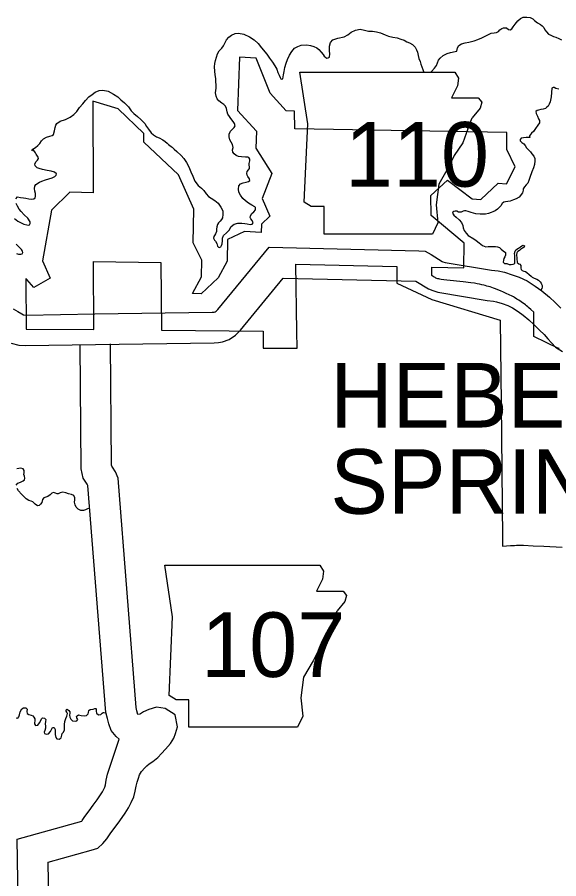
# Model space of a CAD drawing. Extents: x 1212896 to 1368412, y 378476 to 478763.
# Drawn here: x 1234255 to 1239571, y 464301 to 472756 of the extents above; entities that cross this region are included whole.
import ezdxf

# ---------------------------------------------------------------- set-up
doc = ezdxf.new("R2010")
doc.units = 0
for name, color, linetype in [('Level 10', 7, 'Continuous'), ('Level 21', 7, 'Continuous'), ('Level 6', 7, 'Continuous'), ('Level 9', 7, 'Continuous')]:
    doc.layers.add(name, color=color, linetype=linetype)

msp = doc.modelspace()

# ---------------------------------------------------------------- linework, layer by layer
at = {"layer": 'Level 10'}
for points in [[(1234214.4, 469894.6), (1234260.5, 469868.1), (1234301.2, 469844.9), (1234317.3, 469835), (1234318.7, 469834.6), (1234342.9, 469833.1), (1235017.8, 469844.2), (1236168.7, 469859.8), (1236189.6, 469862.4), (1236197.3, 469863.6), (1236206.4, 469869.9), (1236224.5, 469887.4), (1236727.1, 470498.3), (1238195.9, 470464.7), (1238259.5, 470461.2), (1238317.3, 470426.4), (1238425.5, 470360.3), (1238434.6, 470356.7), (1238455.1, 470350.3), (1238911.2, 470273.7), (1238975.9, 470266.3), (1239037.7, 470254.7), (1239113.8, 470228.9), (1239183.7, 470204.8), (1239261.6, 470167.8), (1239340, 470117.4), (1239405.4, 470070.8), (1239479.7, 470009.5), (1239534.3, 469954.7), (1239591.9, 469901.1)], [(1234197.2, 469556.6), (1234270.3, 469537), (1234336.3, 469533), (1235022.2, 469544.3), (1236189.5, 469560.1), (1236230.4, 469565.2), (1236271.4, 469571.3), (1236334.5, 469593.7), (1236397.3, 469637.1), (1236445.3, 469683.6), (1236866.1, 470195), (1238169.3, 470165.3), (1238291.6, 470090.5), (1238335.1, 470073.5), (1238385.2, 470057.8), (1238869.2, 469976.6), (1238930.9, 469969.5), (1238961.5, 469963.7), (1239016.7, 469945.1), (1239070, 469926.6), (1239115.7, 469905), (1239171.8, 469868.9), (1239222.6, 469832.7), (1239277.4, 469787.4), (1239325.8, 469738.9), (1239383.2, 469685.5), (1239426.7, 469641.7), (1239463.4, 469600.5), (1239499.9, 469559.9), (1239539.7, 469517.7), (1239606.3, 469475.2)], [(1234267.2, 463883.5), (1234255.7, 464690.1), (1234887.9, 464865.5), (1234893.6, 464872.6), (1234919.8, 464911.7), (1234960.2, 464967.5), (1235001.2, 465023.2), (1235038.7, 465076.2), (1235066.1, 465115.1), (1235090.9, 465152.6), (1235106, 465180.6), (1235114.9, 465200.2), (1235120.5, 465224.1), (1235128.7, 465267.7), (1235140.3, 465326.1), (1235254.7, 465670.4), (1235224.8, 465697.4), (1235177.9, 465757.2), (1235154.7, 465822.2), (1235140.6, 465873.8), (1235125.8, 465932.4), (1234949.6, 468159.3), (1234940.5, 468172.4), (1234902.8, 468231.5), (1234882.1, 468323.5), (1234871.3, 469543.8)], [(1234567.2, 463887.2), (1234559, 464462.9), (1234981, 464580.1), (1235045.2, 464600.7), (1235097, 464647.4), (1235134.8, 464693.5), (1235166.1, 464740.2), (1235202.6, 464790.8), (1235244.4, 464847.6), (1235283.7, 464903), (1235313.9, 464945.9), (1235348.5, 464998.3), (1235375.1, 465047.6), (1235400.2, 465103.1), (1235414.1, 465161.9), (1235423.3, 465211), (1235430.9, 465249.3), (1235444.2, 465289.3), (1235456.8, 465321.6), (1235476.5, 465354.4), (1235506.2, 465389.6), (1235527.1, 465410.4), (1235549.1, 465427.5), (1235586.9, 465450.5), (1235636.9, 465491.1), (1235671.4, 465529), (1235711.2, 465572.4), (1235759.2, 465629.6), (1235790.9, 465681.2), (1235809.9, 465726.1), (1235827.2, 465792.8), (1235806.1, 465910.4), (1235707.9, 465972.1), (1235620.7, 465984.8), (1235548.1, 465963.2), (1235495.8, 465938.2), (1235464.7, 465918.5), (1235458.1, 465916.5), (1235440.6, 465914.1), (1235430.7, 465950.2), (1235422.9, 465981.2), (1235244.8, 468231.4), (1235221, 468294.6), (1235190.2, 468338.8), (1235183.9, 468348.6), (1235181.8, 468358.2), (1235171.3, 469549.1)]]:
    msp.add_lwpolyline(points, dxfattribs=at)
at = {"layer": 'Level 21'}
for p, q in [((1237106.7, 471710.6), (1237030.5, 472218.1)), ((1237030.5, 472218.1), (1238551.9, 472217.4)), ((1238551.9, 472217.4), (1238587, 472158.9)), ((1238553.2, 472218.1), (1238553.2, 472218.1)), ((1238587, 472158.9), (1238578.5, 472082.8)), ((1238578.5, 472082.8), (1238519.3, 471964.4)), ((1238519.3, 471964.4), (1238781.5, 471964.4)), ((1238781.5, 471964.4), (1238815.4, 471922.1)), ((1238815.4, 471922.1), (1238798.5, 471862.9)), ((1238798.5, 471862.9), (1238722.3, 471769.8)), ((1238680, 471659.8), (1238722.3, 471769.8)), ((1237072.8, 470940.8), (1237106.7, 471710.6)), ((1238680, 471659.8), (1238629.3, 471524.5)), ((1238629.3, 471524.5), (1238544.7, 471397.6)), ((1238544.7, 471397.6), (1238485.5, 471279.2)), ((1238485.5, 471279.2), (1238392.4, 471118.5)), ((1238392.4, 471118.5), (1238367.1, 470915.5)), ((1237140.5, 470898.5), (1237072.8, 470940.8)), ((1237267.4, 470898.5), (1237140.5, 470898.5)), ((1237267.4, 470627.9), (1237267.4, 470898.5)), ((1238367.1, 470915.5), (1238384, 470737.8)), ((1238384, 470737.8), (1238333.2, 470627.9)), ((1238333.2, 470627.9), (1237267.4, 470627.9)), ((1235780.3, 466870.3), (1235704.2, 467377.8)), ((1235704.2, 467377.8), (1237225.5, 467377.1)), ((1237225.5, 467377.1), (1237260.6, 467318.6)), ((1237226.8, 467377.8), (1237226.8, 467377.8)), ((1237260.6, 467318.6), (1237252.1, 467242.5)), ((1237252.1, 467242.5), (1237192.9, 467124)), ((1237192.9, 467124), (1237455.2, 467124)), ((1237455.2, 467124), (1237489, 467081.8)), ((1237489, 467081.8), (1237472.1, 467022.5)), ((1237472.1, 467022.5), (1237395.9, 466929.5)), ((1237353.6, 466819.5), (1237395.9, 466929.5)), ((1235746.4, 466100.5), (1235780.3, 466870.3)), ((1237353.6, 466819.5), (1237302.9, 466684.2)), ((1237302.9, 466684.2), (1237218.3, 466557.3)), ((1237218.3, 466557.3), (1237159.1, 466438.9)), ((1237159.1, 466438.9), (1237066, 466278.2)), ((1237066, 466278.2), (1237040.7, 466075.1)), ((1235814.1, 466058.2), (1235746.4, 466100.5)), ((1237040.7, 466075.1), (1237057.6, 465897.5)), ((1235941, 466058.2), (1235814.1, 466058.2)), ((1235941, 465787.5), (1235941, 466058.2)), ((1237057.6, 465897.5), (1237006.8, 465787.5)), ((1237006.8, 465787.5), (1235941, 465787.5))]:
    msp.add_line(p, q, dxfattribs=at)
at = {"layer": 'Level 6'}
for points in [[(1238318.5, 470811.5), (1238316.3, 471007.2), (1238478.4, 471158.3), (1238722.2, 470974.7), (1238805.6, 470968.8), (1238977.5, 471129.1), (1239059, 471122), (1239142.8, 471286.4), (1239062.8, 471458), (1239062.8, 471625), (1236979, 471660), (1236977.5, 471832.6), (1236894.4, 471837), (1236737.1, 472011.7), (1236602.2, 472355.5), (1236436.6, 472364.1), (1236419, 471841), (1236602.4, 471637.4), (1236596.5, 471470.9), (1236753.8, 471222.9), (1236659.5, 470977.2), (1236736.3, 470804.8), (1236651.6, 470725.9), (1236650.2, 470643.4), (1236484.9, 470652), (1236318.6, 470574.5), (1236314.9, 470360.4), (1236228.9, 470198.6), (1236059.7, 470040.9), (1235977.2, 470045.3), (1236063.1, 470206.9), (1236066, 470372.2), (1235982.4, 470543.5), (1235988.2, 470872.5), (1235838, 471209.9), (1235499.3, 471531), (1235498.9, 471613.3), (1235247.5, 471856.6), (1234998.4, 471933.1), (1235000.5, 471034.2), (1234770.8, 471037.8), (1234590.9, 470864), (1234503.2, 470366.6), (1234579.4, 470195.2), (1234419, 470103.2), (1234349.2, 470180.7), (1234339.9, 470191)], [(1239574.6, 469511.9), (1239569.6, 469503.5), (1239327.2, 469621.5), (1239324.9, 469862), (1239297.6, 469887.8), (1239278.6, 469904.4), (1239267.5, 469913.4), (1239255.3, 469923.1), (1239243, 469932.7), (1239230, 469942.3), (1239216.1, 469952.1), (1239201.4, 469962.6), (1239178.5, 469977.9), (1239160.1, 469989.7), (1239135.8, 470004.4), (1239125.7, 470010.3), (1239112.1, 470017.7), (1239082.6, 470033.1), (1239056.2, 470045.7), (1239027.9, 470058.6), (1238999.8, 470070.7), (1238973.7, 470081.1), (1238949, 470090.6), (1238931.5, 470096.8), (1238914.7, 470102.6), (1238897.1, 470108.5), (1238881.5, 470113.3), (1238865.5, 470118), (1238849.4, 470122.3), (1238834.6, 470126.2), (1238816.5, 470130.3), (1238793.1, 470135.6), (1238770.4, 470139.9), (1238742.7, 470144.5), (1238707, 470149.4), (1238632.6, 470158.3), (1238473.8, 470176.5), (1238442.8, 470180.2), (1238416.3, 470183.3), (1238404.6, 470185.1), (1238394.2, 470187.3), (1238384.3, 470190.1), (1238374.5, 470193.1), (1238365.9, 470196.2), (1238356.6, 470200.2), (1238346.5, 470206.1), (1238337.9, 470211.6), (1238329.3, 470217.5), (1238325.1, 470220.3), (1238324.1, 470301.9), (1238640.2, 470295), (1238642.8, 470539.4), (1238318.5, 470811.5)], [(1234339.9, 470191), (1234341.5, 469696), (1235008.6, 469689.9), (1235002.2, 470359.4), (1235665, 470350), (1235672.4, 469683.8), (1236668.2, 469674.6), (1236670.3, 469509.4), (1237002.4, 469506.8), (1237000.1, 469671.6), (1236991, 470331), (1237981, 470309.4), (1237982.8, 470146.1), (1238326.2, 469986.6), (1238996, 469782.8), (1239004.4, 468968.1), (1239018, 467644.9), (1239018.7, 467565.2), (1239097.5, 467570.2), (1239135.8, 467572.9), (1239156.7, 467574.5), (1239175.7, 467575.1), (1239194.7, 467575.1), (1239224.1, 467573.8), (1239319.5, 467568.9), (1239423.7, 467563.7), (1239603.4, 467554.2)]]:
    msp.add_lwpolyline(points, dxfattribs=at)
at = {"layer": 'Level 9'}
for points in [[(1238319.9, 472211.7), (1238322.8, 472224.2), (1238351, 472255.9), (1238370.4, 472281.5), (1238380.7, 472309.8), (1238392.1, 472334.1), (1238407.6, 472355.6), (1238435, 472380.3), (1238474.5, 472400.3), (1238507.3, 472410.1), (1238553.1, 472420.2), (1238571, 472423.7), (1238574.7, 472437.8), (1238577.2, 472456.9), (1238588.7, 472477.2), (1238617.2, 472496), (1238651, 472505.8), (1238688.9, 472509.7), (1238739.6, 472523), (1238775.3, 472535.9), (1238815.9, 472553.9), (1238855.4, 472573.9), (1238880.1, 472587.5), (1238908.8, 472599.2), (1238937.7, 472603.9), (1238958.7, 472605.4), (1238978.4, 472616.9), (1238994, 472633.4), (1239011.7, 472646.8), (1239028.6, 472652.2), (1239056.6, 472652.9), (1239078, 472636.4), (1239093.1, 472633.7), (1239110.8, 472643.2), (1239124.4, 472661.6), (1239142.7, 472688.1), (1239169, 472719.8), (1239195.4, 472742.5), (1239220.1, 472755.1), (1239259.1, 472756), (1239291.2, 472751.8), (1239315.5, 472741.4), (1239334, 472722.7), (1239363.5, 472702.4), (1239393, 472683.1), (1239407.2, 472672.4), (1239423.7, 472653.7), (1239434.2, 472633.9), (1239449.8, 472611.2), (1239471.3, 472590.7), (1239492.6, 472580.2), (1239519.9, 472567.8), (1239542.1, 472560.3), (1239570.4, 472548.9), (1239597.7, 472534.6)], [(1236368.6, 471506.4), (1236343.4, 471553.9), (1236334.8, 471581.8), (1236336.1, 471609.9), (1236349.4, 471638.3), (1236369.9, 471656.8), (1236384.5, 471674.2), (1236393.1, 471690.5), (1236388.5, 471713.4), (1236375, 471734.2), (1236353.3, 471761.7), (1236337.9, 471780.4), (1236323.3, 471803.1), (1236316.7, 471828), (1236310.9, 471859), (1236300.3, 471882.8), (1236283.9, 471900.4), (1236262.5, 471914), (1236233, 471935.3), (1236217.5, 471955), (1236206.8, 471981.8), (1236202, 472013.8), (1236206.9, 472060), (1236204.6, 472154.2), (1236198.6, 472192.2), (1236193.7, 472227.2), (1236190.7, 472268.2), (1236193.9, 472300.4), (1236201.1, 472332.6), (1236211.3, 472365), (1236221.5, 472398.3), (1236238.9, 472425.8), (1236262.2, 472452.4), (1236278.6, 472476.9), (1236294.9, 472507.3), (1236310.2, 472535.8), (1236333.6, 472561.4), (1236357.1, 472579), (1236394.8, 472595), (1236426.6, 472600.8), (1236480.9, 472589), (1236534.6, 472563.2), (1236580.3, 472534.3), (1236620.3, 472497.1), (1236654.3, 472456.8), (1236706.9, 472392.9), (1236730.8, 472355.4), (1236761.9, 472314), (1236784.7, 472280.5), (1236804.5, 472246.8), (1236813.4, 472213), (1236825.1, 472186.2), (1236837.6, 472165.4), (1236843.9, 472152.5), (1236852, 472146.7), (1236860.9, 472151.9), (1236870, 472190.3), (1236876.1, 472224.5), (1236882.2, 472263.8), (1236894.2, 472304.2), (1236908.3, 472341.6), (1236929.2, 472383.2), (1236949.3, 472419.8), (1236976.5, 472452.5), (1237011.1, 472469.4), (1237043.8, 472482.2), (1237098.8, 472486.5), (1237135, 472479.4), (1237166.2, 472470.1), (1237196.6, 472455.8), (1237215, 472439.2), (1237237.6, 472413.7), (1237258.2, 472390.1), (1237268.6, 472374.3), (1237283, 472360.6), (1237295.1, 472354.9), (1237308.1, 472357.2), (1237321.9, 472365.6), (1237325.1, 472396.7), (1237321.3, 472427.7), (1237321.3, 472470.8), (1237330.3, 472508.2), (1237352.7, 472533.8), (1237403.3, 472551), (1237464, 472564.5), (1237501.6, 472583.5), (1237533, 472608.3), (1237574.5, 472628.3), (1237621.3, 472637.5), (1237665.5, 472630.5), (1237702.8, 472618.4), (1237742.8, 472619.3), (1237781.9, 472614.3), (1237821.2, 472604.2), (1237867.7, 472583.2), (1237899, 472571), (1237943.3, 472561), (1237983.5, 472552.9), (1238021.8, 472541.8), (1238052.1, 472529.5), (1238078.5, 472516.1)], [(1238078.5, 472516.1), (1238105.8, 472503.7), (1238136.2, 472488.4), (1238160.8, 472462.9), (1238175.5, 472437.2), (1238184.1, 472412.4), (1238191.9, 472380.5), (1238198.7, 472349.5), (1238209.4, 472321.7), (1238218, 472294.8), (1238225.6, 472270), (1238235.3, 472244.1), (1238241.8, 472224.2), (1238246.1, 472210.4)], [(1234397.2, 471446), (1234409.9, 471460.3), (1234433.4, 471479), (1234458, 471496.6), (1234475.5, 471518.1), (1234491.9, 471542.5), (1234513.3, 471564.1), (1234542, 471577.8), (1234575.8, 471587.7), (1234598.6, 471594.2), (1234612.3, 471606.6), (1234621.5, 471640.9), (1234628.7, 471673.2), (1234634.2, 471695.4), (1234643.7, 471713.6), (1234677.2, 471734.5), (1234728.8, 471753.8), (1234776.3, 471775), (1234811.7, 471799.9), (1234838.9, 471829.6), (1234866, 471869.4), (1234898, 471907.2), (1234926.2, 471940), (1234959.4, 471973.9), (1234989.8, 471998.7), (1235020.3, 472019.5), (1235058, 472035.4), (1235094.8, 472040.3), (1235148.1, 472031.6), (1235199.9, 472001.7), (1235241.5, 471975.7), (1235273.3, 471946.3), (1235307, 471915.1), (1235347, 471875.9), (1235375, 471838.5), (1235398.7, 471811), (1235434.4, 471780.8), (1235468.1, 471752.5), (1235507.1, 471712.3), (1235524.9, 471683.7), (1235542.6, 471656), (1235568.4, 471622.5), (1235592.9, 471601.1), (1235623.4, 471583.8), (1235649.7, 471571.3), (1235683.2, 471553.1), (1235707.6, 471536.6), (1235728, 471521.1), (1235739.3, 471508.3), (1235765.8, 471487.9)], [(1239515.3, 472065.3), (1239504.4, 472059), (1239497.5, 471975.6), (1239485.7, 471927.2), (1239475.3, 471901.9), (1239465.8, 471883.6), (1239450.1, 471869.2), (1239439.3, 471861.9), (1239417.5, 471853.4), (1239395.6, 471848.9), (1239371.7, 471845.3), (1239357.7, 471841.9), (1239347, 471831.6), (1239350.5, 471811.7), (1239361.2, 471783.9), (1239373.8, 471760.1), (1239381.2, 471741.2), (1239380.7, 471721.2), (1239366.3, 471696.7), (1239344.1, 471665.1), (1239322.8, 471635.5), (1239303.2, 471618), (1239284.9, 471591.5)], [(1239572.7, 472050.6), (1239542.5, 472057.9), (1239526.3, 472065.6), (1239515.3, 472065.3)], [(1239284.9, 471591.5), (1239287.4, 471574.3), (1239269.3, 471576.8), (1239252.3, 471577.3), (1239224.5, 471573.5), (1239202.6, 471568.9), (1239191, 471555.6), (1239192.3, 471543.6), (1239209.8, 471527), (1239228.1, 471514.5), (1239239.7, 471496.8), (1239254.3, 471475.2), (1239275.9, 471451.7), (1239292.4, 471434.2), (1239307, 471414.5), (1239325.6, 471393), (1239336.3, 471370.3), (1239336.9, 471347.2), (1239331.9, 471312), (1239323.9, 471278.7), (1239307, 471240.2), (1239286.7, 471182.5), (1239278.5, 471152.2), (1239266.3, 471126.8), (1239249.8, 471110.3), (1239233.3, 471091.8), (1239221.8, 471073.4), (1239220.3, 471058.4), (1239214, 471032.1), (1239181.2, 470991.1), (1239151.8, 470972.3), (1239126.1, 470962.5), (1239095.4, 470949.6), (1239070.5, 470948.9), (1239049.6, 470945.3), (1239030.7, 470939.8), (1239017.1, 470927.4), (1239000.8, 470904.9), (1238984.3, 470885.4), (1238969.7, 470871.9), (1238947.1, 470857.3), (1238924.5, 470845.6), (1238906.7, 470840.1), (1238881.9, 470831.4), (1238851.1, 470824.5), (1238800.2, 470823), (1238758.1, 470826.9), (1238711.7, 470840.6), (1238681.4, 470850.8), (1238660.3, 470856.2), (1238644.3, 470855.7), (1238632.4, 470851.4), (1238620.6, 470845), (1238611.7, 470841.8), (1238597.7, 470841.4), (1238586.7, 470843.1), (1238569.4, 470851.6), (1238555.4, 470853.2), (1238539.5, 470849.8), (1238530.7, 470843.5), (1238527, 470832.4), (1238539.5, 470813.7), (1238565.1, 470792.4), (1238592.8, 470768.1), (1238617.6, 470740.7), (1238630.5, 470711), (1238634.1, 470688.1), (1238643.8, 470663.3), (1238661.6, 470636.8), (1238683.2, 470614.3), (1238738.2, 470580.8), (1238761.7, 470563.4), (1238790.3, 470541.2), (1238821, 470516), (1238855.4, 470501.9), (1238879.3, 470504.6), (1238914.3, 470505.6), (1238949.2, 470506.6), (1238971.3, 470503.2), (1238990.6, 470494.7), (1239005, 470478.1), (1239024.4, 470463.6), (1239046.9, 470447.2), (1239046.6, 470421.2), (1239041.1, 470405), (1239032.6, 470388.7), (1239028.1, 470370.5), (1239026.7, 470351.5), (1239040, 470339.8), (1239060, 470338.4), (1239083.3, 470330), (1239104.3, 470328.6), (1239123.1, 470333.1), (1239140, 470338.6), (1239138.7, 470418.8), (1239138.2, 470436.8), (1239141.5, 470458.9), (1239151.1, 470473.2), (1239176.6, 470490), (1239195.3, 470501.5), (1239208, 470511.9)], [(1235765.8, 471487.9), (1235775.4, 471480.2), (1235796.9, 471460.8), (1235820.6, 471438.4), (1235863.7, 471399.5), (1235889.6, 471368.2), (1235915.7, 471328.8), (1235938.8, 471288.4), (1235959.2, 471239.9), (1235977.5, 471196.3), (1235999.9, 471145.8), (1236031.1, 471105.6), (1236064.8, 471079.5), (1236086.5, 471055.1), (1236108.4, 471023.6), (1236132.2, 470996.2), (1236158.7, 470979), (1236196.2, 470958), (1236227, 470929.8), (1236255.1, 470891.5), (1236272.1, 470856.9), (1236274.2, 470819.9), (1236271.1, 470787.7), (1236261.6, 470770.4), (1236246.1, 470754), (1236231.5, 470739.5), (1236220, 470721.2), (1236214.7, 470698), (1236211.4, 470674.8), (1236210, 470654.7), (1236201.6, 470631.5), (1236192.1, 470614.2), (1236185.5, 470602.9), (1236180.9, 470588.8), (1236190.4, 470569), (1236201.8, 470557.3), (1236213.4, 470536.6), (1236222.1, 470509.8), (1236229.4, 470500), (1236236.5, 470497.2), (1236252.3, 470502.6), (1236261.9, 470515.9), (1236267.4, 470533.1), (1236268.6, 470562.2), (1236270.9, 470586.3), (1236281.1, 470614.7), (1236309.4, 470639.5), (1236334.6, 470665.3), (1236354.5, 470702.9), (1236385.9, 470724.8), (1236421.6, 470734.9), (1236459.6, 470733.9), (1236489.6, 470732.8), (1236513.8, 470727.4), (1236540.9, 470723.2), (1236559.8, 470724.7), (1236570.4, 470739.1), (1236562.7, 470761.9), (1236547.3, 470776.5), (1236541, 470789.3), (1236543.4, 470808.4), (1236558.8, 470829.9), (1236578.3, 470846.5), (1236594.7, 470866), (1236595.1, 470889.1), (1236587.9, 470893.9), (1236559.4, 470912.1), (1236526.9, 470931.2), (1236494.3, 470953.4), (1236468.6, 470976.7), (1236446.7, 471008.1), (1236431.8, 471038.8), (1236426, 471067.7), (1236431.1, 471099.9), (1236447.5, 471120.4), (1236473.2, 471131.1), (1236501, 471136.9), (1236525.8, 471143.6), (1236537.5, 471155), (1236535, 471171), (1236518.3, 471194.5), (1236511, 471205.3), (1236509.5, 471222.3), (1236513, 471240.5), (1236525.5, 471257.9), (1236536.1, 471271.2), (1236535.6, 471288.2), (1236532.2, 471303.1), (1236532.7, 471320.2), (1236535.3, 471333.3), (1236538, 471346.4), (1236538.5, 471363.4), (1236530, 471378.2), (1236518.9, 471382.9), (1236496.9, 471382.3), (1236456.8, 471386.2), (1236428.7, 471390.4), (1236403.5, 471398.7), (1236383.1, 471414.2), (1236371.5, 471432.9), (1236368.9, 471454.9)], [(1236368.9, 471454.9), (1236374.3, 471476), (1236368.6, 471506.4)], [(1234623.1, 471192.1), (1234637.7, 471204.6), (1234639.3, 471218.6), (1234619.8, 471236.1), (1234588.6, 471245.3), (1234548.4, 471253.2), (1234504.1, 471260.9), (1234469.9, 471270), (1234449.6, 471279.4), (1234432.2, 471296), (1234429.5, 471317.9), (1234441.9, 471341.3), (1234455.5, 471353.7), (1234465, 471370.1), (1234461.6, 471384), (1234447.1, 471401.6), (1234439.8, 471412.4), (1234434.4, 471426.3), (1234409.9, 471460.3)], [(1234241.5, 470974.9), (1234259, 470992.5), (1234286.1, 470987.2), (1234316.2, 470982.1), (1234338.3, 470978.7), (1234370.5, 470973.6), (1234399.5, 470971.4), (1234419.4, 470975), (1234430.2, 470983.3), (1234435.7, 471000.5), (1234435, 471024.5), (1234429.3, 471048.4), (1234425.5, 471075.3), (1234428.9, 471097.5), (1234438.4, 471114.8), (1234472.8, 471135.8), (1234497.4, 471147.5), (1234532, 471160.5), (1234565.7, 471170.5), (1234597.4, 471180.4), (1234623.1, 471192.1)], [(1234227.1, 470780.1), (1234261.8, 470755.1), (1234294.3, 470736.9), (1234319.6, 470725.6), (1234350.8, 470717.5), (1234366.9, 470715.9), (1234376.8, 470717.2), (1234382.4, 470730.4), (1234380.9, 470748.4), (1234357.9, 470782.8), (1234324, 470816.9), (1234294.1, 470849.2), (1234275.4, 470873.7), (1234256.6, 470900.2), (1234244.8, 470928.9)], [(1234247.9, 470438), (1234268.1, 470431.6), (1234292.1, 470430.3), (1234304, 470433.6), (1234311.7, 470445.8), (1234308.2, 470460.8), (1234296.7, 470477.5), (1234272, 470502.8), (1234243.3, 470528.1)], [(1239208, 470511.9), (1239213.8, 470517.1), (1239222.8, 470519.3), (1239234, 470511.6), (1239230.3, 470500.5), (1239214.6, 470490), (1239197, 470477.5), (1239185.2, 470468.2), (1239168.6, 470457.7), (1239162.7, 470451.5), (1239160, 470442.4), (1239156.4, 470427.3), (1239163.7, 470347.3), (1239180, 470336.8), (1239190.2, 470331), (1239198.5, 470320.2), (1239198.9, 470306.2), (1239199.2, 470294.2), (1239202.6, 470280.3), (1239210.9, 470270.5), (1239228.1, 470264), (1239244.2, 470259.4), (1239257.4, 470251.8), (1239281, 470231.4), (1239300.5, 470213.9), (1239310.7, 470206.2), (1239331, 470195.7), (1239357.3, 470185.4), (1239373.6, 470174.9), (1239388.1, 470159.3), (1239398.5, 470144.5), (1239402.7, 470137.6), (1239407.1, 470122.7), (1239406.6, 470105.7), (1239403.9, 470094.6), (1239396.3, 470081.3), (1239394.8, 470079.5)], [(1234245.3, 468164.3), (1234259.8, 468181.7), (1234288.4, 468193.6), (1234314.1, 468205.3), (1234327.7, 468216.7), (1234330.3, 468231.8), (1234325.7, 468251.7), (1234321.2, 468268.7), (1234322.7, 468285.7), (1234323.1, 468306.8), (1234312.7, 468323.5), (1234291.5, 468328.9), (1234250.7, 468323.8)], [(1234579.9, 468068.5), (1234556.4, 468052.8), (1234534.6, 468046.2), (1234516.8, 468038.7), (1234503.2, 468024.3), (1234495.1, 467994), (1234484.6, 467975.7), (1234468.9, 467964.2), (1234455, 467961.8), (1234429.6, 467978.1), (1234408.9, 467999.6), (1234392.8, 468005.1), (1234370.6, 468011.5), (1234343.1, 468029.8), (1234319.5, 468052.2), (1234296.9, 468073.6), (1234267.9, 468106.8), (1234253.2, 468131.5)], [(1234964.3, 467934.7), (1234944.7, 467932.5), (1234924, 467921.9), (1234905.2, 467914.4), (1234880.2, 467915.7), (1234854.8, 467929), (1234834.3, 467947.4), (1234822.6, 467970.2), (1234816.9, 467996.1), (1234819.3, 468018.2), (1234819.7, 468038.2), (1234810, 468063), (1234786.7, 468073.4), (1234759.6, 468077.6), (1234731.3, 468086.8), (1234703.1, 468094.1), (1234675.3, 468087.3), (1234658.5, 468079.8), (1234646.6, 468079.4), (1234632.4, 468086), (1234612.2, 468091.5), (1234596.4, 468085), (1234579.9, 468068.5)], [(1234245, 465878.6), (1234261, 465877.1), (1234271.6, 465890.4), (1234277, 465910.6), (1234285.3, 465937.9), (1234301.4, 465967.4), (1234315.1, 465978.8), (1234338, 465979.4), (1234351.4, 465965.8), (1234348.1, 465941.6), (1234351.7, 465922.7), (1234368.9, 465914.2), (1234392.1, 465907.8), (1234407.3, 465899.2), (1234417.7, 465885.5), (1234427.2, 465868.7), (1234427.7, 465851.7), (1234424.3, 465831.6), (1234425.6, 465820.6), (1234435, 465805.8), (1234455.9, 465808.4), (1234475.3, 465831), (1234486.6, 465853.4), (1234494.1, 465871.6), (1234503.8, 465879.9), (1234521.9, 465877.4), (1234534.3, 465864.7), (1234532.8, 465844.7), (1234529.5, 465822.5), (1234533.2, 465798.6), (1234533.8, 465777.5), (1234525.4, 465756.3), (1234520.9, 465740.1), (1234522.2, 465727.1), (1234540.5, 465718.6), (1234561.3, 465724.2), (1234580.7, 465744.8), (1234591.1, 465766.1), (1234601.6, 465784.5), (1234616.5, 465784.9), (1234627.1, 465764.1), (1234626.8, 465740.1), (1234626.5, 465717), (1234633.3, 465687.2)], [(1234633.3, 465687.2), (1234643.7, 465674.4), (1234666.8, 465671.1), (1234687.5, 465682.7), (1234693.7, 465709.9), (1234697.2, 465725), (1234708.8, 465739.4), (1234718.2, 465761.7), (1234718.3, 465790.8), (1234719.6, 465815.9), (1234723.8, 465845), (1234732, 465873.3), (1234742.3, 465895.7), (1234746.9, 465909.8), (1234747.5, 465923.9), (1234742.2, 465935.7), (1234736.9, 465944.6), (1234735.7, 465952.6), (1234738.4, 465961.7), (1234745.3, 465963.9), (1234761.7, 465951.3), (1234771.1, 465938.6), (1234772.5, 465924.6), (1234769, 465906.4), (1234770.5, 465887.4), (1234780.2, 465865.7), (1234798.6, 465849.1), (1234823.7, 465847.9), (1234840.6, 465849.3), (1234849.2, 465862.6), (1234847, 465871.6), (1234841.7, 465881.4), (1234838.4, 465892.4), (1234844.1, 465900.5), (1234855.9, 465907.9), (1234884.1, 465901.7), (1234912.1, 465899.4), (1234935, 465904.1), (1234950.6, 465918.6), (1234955.2, 465932.7), (1234959.6, 465950.9), (1234971.3, 465962.2), (1235000.2, 465966.1), (1235017, 465971.6), (1235026, 465971.8), (1235029.1, 465967.9), (1235030.4, 465958.9), (1235030.8, 465943.9), (1235034.3, 465926.9), (1235051.8, 465909.4), (1235075.7, 465914.1), (1235087.3, 465926.4), (1235100.1, 465933.8), (1235104.1, 465932.9), (1235120.2, 465928.4), (1235130, 465919.2)]]:
    msp.add_lwpolyline(points, dxfattribs=at)

# ---------------------------------------------------------------- texts
at = {"layer": 'Level 21'}
for s, p in [('110', (1237472.5, 471093.6)), ('107', (1236061.1, 466281.3))]:
    msp.add_text(s, height=633.6, dxfattribs=at).set_placement(p)
at = {"layer": 'Level 6'}
for s, p in [('HEBER', (1237328.1, 468729.2)), ('SPRINGS', (1237329.1, 467882.7))]:
    msp.add_text(s, height=633.6, dxfattribs=at).set_placement(p)

doc.saveas('drawing.dxf')
